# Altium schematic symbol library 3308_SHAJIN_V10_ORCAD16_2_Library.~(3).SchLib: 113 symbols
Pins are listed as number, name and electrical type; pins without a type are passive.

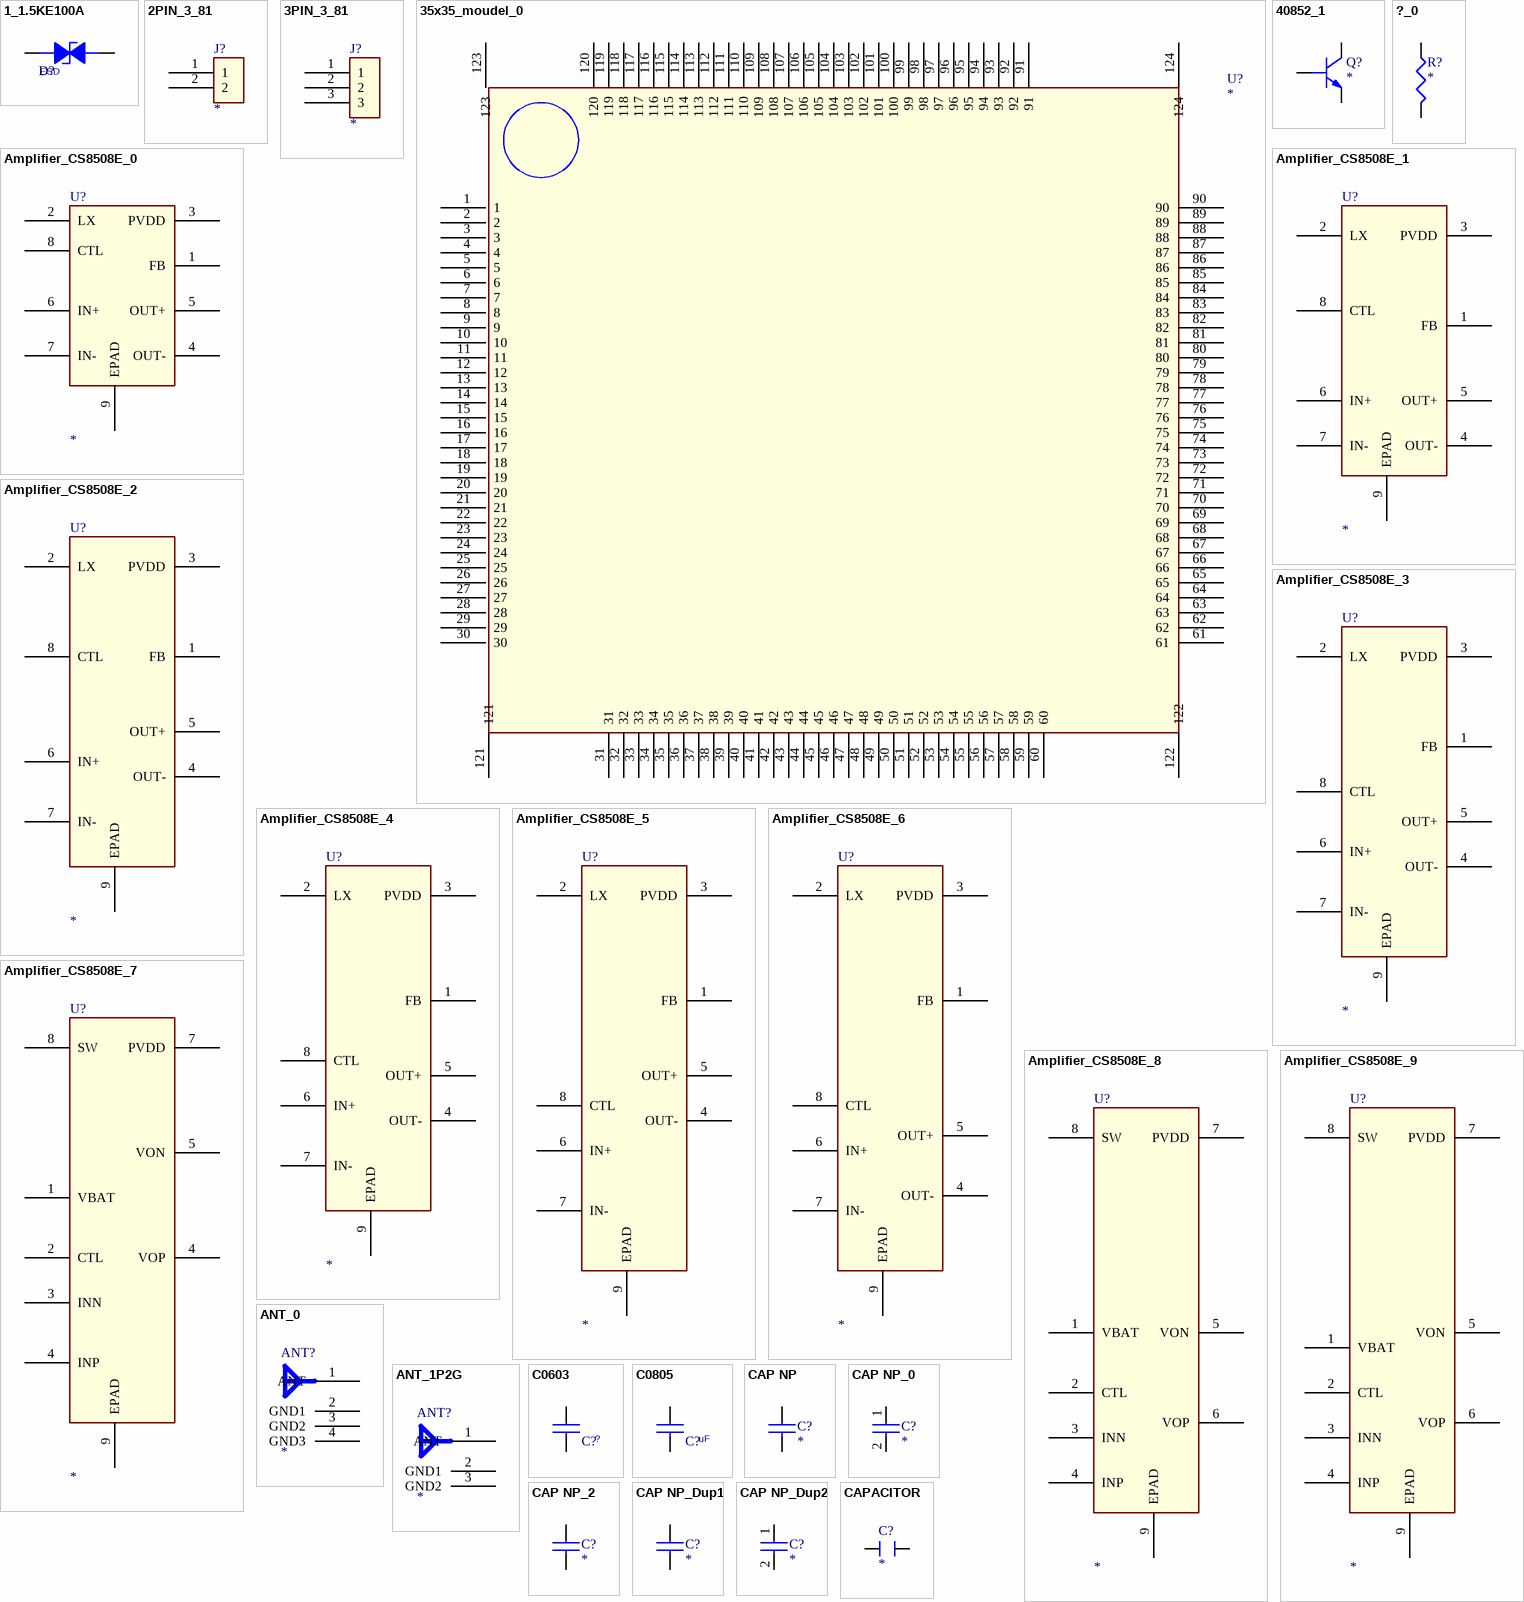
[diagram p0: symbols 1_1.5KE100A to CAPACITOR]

## 1_1.5KE100A
designator D?, comment ESD
Altium-Right: 40; Altium-Bottom: 20
pins: 1 ANODE, 2 CATHODE

## 2PIN_3_81
designator J?
Altium-Right: 50
footprint 2PIN_3_81
pins: 1, 2

## 3PIN_3_81
designator J?
Altium-Right: 50
footprint 3PIN_3_81
pins: 1, 2, 3

## 35x35_moudel_0
designator U?
Altium-Right: 462; Altium-Bottom: 430
footprint 35x35_moudel
pins: 1, 2, 3, 4, 5, 6, 7, 8, 9, 10, 11, 12, 13, 14, 15, 16, 17, 18, 19, 20, 21, 22, 23, 24, 25, 26, 27, 28, 29, 30, 31, 32, 33, 34, 35, 36, 37, 38, 39, 40, 41, 42, 43, 44, 45, 46, 47, 48, 49, 50, 51, 52, 53, 54, 55, 56, 57, 58, 59, 60, 61, 62, 63, 64, 65, 66, 67, 68, 69, 70, 71, 72, 73, 74, 75, 76, 77, 78, 79, 80, 81, 82, 83, 84, 85, 86, 87, 88, 89, 90, 91, 92, 93, 94, 95, 96, 97, 98, 99, 100, 101, 102, 103, 104, 105, 106, 107, 108, 109, 110, 111, 112, 113, 114, 115, 116, 117, 118, 119, 120, 121, 122, 123, 124

## 40852_1
designator Q?
Altium-Right: 20
pins: 1 B, 2 E, 3 C

## ?_0
designator R?
Altium-Right: 20; Altium-Bottom: 30
footprint R0402
pins: 1, 2

## Amplifier_CS8508E_0
designator U?
Altium-Right: 70; Altium-Bottom: 120
pins: 1 FB, 2 LX, 3 PVDD, 4 OUT-, 5 OUT+, 6 IN+, 7 IN-, 8 CTL, 9 EPAD

## Amplifier_CS8508E_1
designator U?
Altium-Right: 70; Altium-Bottom: 180
pins: 1 FB, 2 LX, 3 PVDD, 4 OUT-, 5 OUT+, 6 IN+, 7 IN-, 8 CTL, 9 EPAD

## Amplifier_CS8508E_2
designator U?
Altium-Right: 70; Altium-Bottom: 220
pins: 1 FB, 2 LX, 3 PVDD, 4 OUT-, 5 OUT+, 6 IN+, 7 IN-, 8 CTL, 9 EPAD

## Amplifier_CS8508E_3
designator U?
Altium-Right: 70; Altium-Bottom: 220
pins: 1 FB, 2 LX, 3 PVDD, 4 OUT-, 5 OUT+, 6 IN+, 7 IN-, 8 CTL, 9 EPAD

## Amplifier_CS8508E_4
designator U?
Altium-Right: 70; Altium-Bottom: 230
pins: 1 FB, 2 LX, 3 PVDD, 4 OUT-, 5 OUT+, 6 IN+, 7 IN-, 8 CTL, 9 EPAD

## Amplifier_CS8508E_5
designator U?
Altium-Right: 70; Altium-Bottom: 270
pins: 1 FB, 2 LX, 3 PVDD, 4 OUT-, 5 OUT+, 6 IN+, 7 IN-, 8 CTL, 9 EPAD

## Amplifier_CS8508E_6
designator U?
Altium-Right: 70; Altium-Bottom: 270
pins: 1 FB, 2 LX, 3 PVDD, 4 OUT-, 5 OUT+, 6 IN+, 7 IN-, 8 CTL, 9 EPAD

## Amplifier_CS8508E_7
designator U?
Altium-Right: 70; Altium-Bottom: 270
pins: 1 VBAT, 2 CTL, 3 INN, 4 INP, 4 VOP, 5 VON, 7 PVDD, 8 SW, 9 EPAD

## Amplifier_CS8508E_8
designator U?
Altium-Right: 70; Altium-Bottom: 270
pins: 1 VBAT, 2 CTL, 3 INN, 4 INP, 5 VON, 6 VOP, 7 PVDD, 8 SW, 9 EPAD

## Amplifier_CS8508E_9
designator U?
Altium-Right: 70; Altium-Bottom: 270
pins: 1 VBAT, 2 CTL, 3 INN, 4 INP, 5 VON, 6 VOP, 7 PVDD, 8 SW, 9 EPAD

## ANT_0
designator ANT?
Altium-Right: 30; Altium-Bottom: 60
pins: 1 ANT, 2 GND1, 3 GND2, 4 GND3

## ANT_1P2G
designator ANT?
Altium-Right: 30; Altium-Bottom: 50
pins: 1 ANT, 2 GND1, 3 GND2

## C0603
designator C?, comment ?
Altium-Right: 20; Altium-Bottom: 10
footprint C0603
pins: 1, 2

## C0805
designator C?, comment uF
Altium-Right: 20; Altium-Bottom: 10
footprint C0805
pins: 1, 2

## CAP NP
designator C?
Altium-Right: 20; Altium-Bottom: 10
pins: 1, 2

## CAP NP_0
designator C?
Altium-Right: 20; Altium-Bottom: 10
pins: 1, 2

## CAP NP_2
designator C?
Altium-Right: 20; Altium-Bottom: 10
pins: 1, 2

## CAP NP_Dup1
designator C?
Altium-Right: 20; Altium-Bottom: 10
footprint C0402
pins: 1, 2

## CAP NP_Dup2
designator C?
Altium-Right: 20; Altium-Bottom: 10
pins: 1, 2

## CAPACITOR
designator C?
Altium-Right: 10; Altium-Bottom: 20
pins: 1, 2

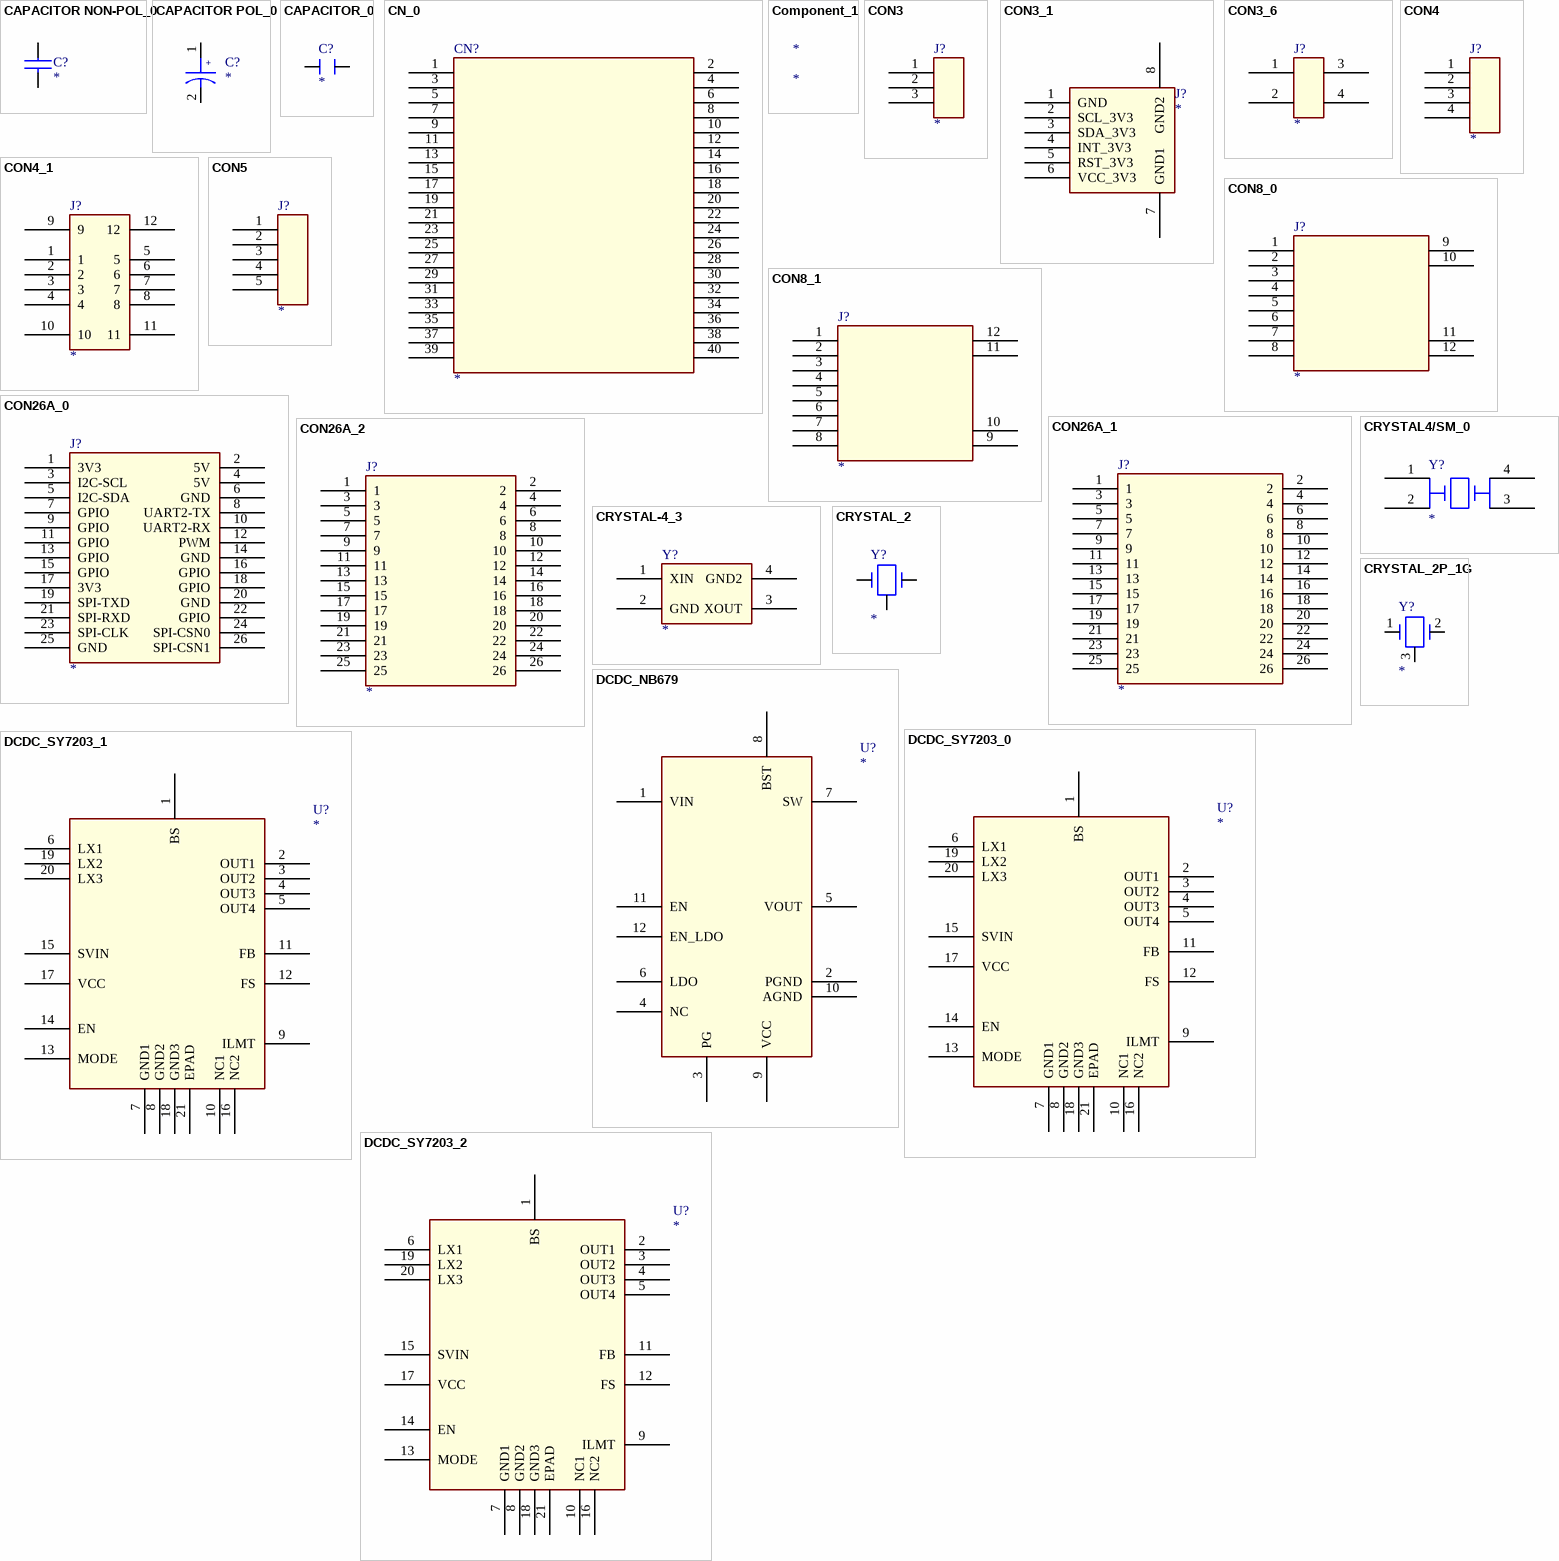
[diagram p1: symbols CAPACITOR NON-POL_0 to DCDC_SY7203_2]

## CAPACITOR NON-POL_0
designator C?
Altium-Right: 20; Altium-Bottom: 10
pins: 1, 2

## CAPACITOR POL_0
designator C?
Altium-Right: 20
pins: 1, 2

## CAPACITOR_0
designator C?
Altium-Right: 10; Altium-Bottom: 20
pins: 1, 2

## CN_0
designator CN?
Altium-Right: 160; Altium-Bottom: 210
pins: 1 GND, 2 GND, 3 UART0-CTS, 4 PWR-BTN-N, 5 UART0-TX, 6 RST-BTN-N, 7 UART0-RX, 8 SPI0-SCLK, 9 UART0-RTS, 10 SPI0-DIN, 11 UART1-TX, 12 SPI0-CS, 13 UART1-RX, 14 SPI0-DOUT, 15 I2C0-SCL, 16 PCM-FS/I2S-WC, 17 I2C0-SDA, 18 PCM-CLK/I2S-BC, 19 I2C1-SCL, 20 PCM-DO/I2S-DO, 21 I2C1-SDA, 22 PCM-DI/I2S-DI, 23 GPIO-A, 24 GPIO-B, 25 GPIO-C, 26 GPIO-D, 27 GPIO-E, 28 GPIO-F, 29 GPIO-G, 30 GPIO-H, 31 GPIO-I, 32 GPIO-J, 33 GPIO-K, 34 GPIO-L, 35 +1V8, 36 SYS-DCIN, 37 +5V, 38 SYS-DCIN, 39 GND, 40 GND

## Component_1
designator *

## CON3
designator J?
Altium-Right: 20; Altium-Bottom: 40
pins: 1, 2, 3

## CON3_1
designator J?
Altium-Right: 70
footprint DIP3_1X3_2R54
pins: 1 GND, 2 SCL_3V3, 3 SDA_3V3, 4 INT_3V3, 5 RST_3V3, 6 VCC_3V3, 7 GND1, 8 GND2

## CON3_6
designator J?
Altium-Right: 20; Altium-Bottom: 40
pins: 1, 2, 3, 4

## CON4
designator J?
Altium-Right: 20; Altium-Bottom: 50
pins: 1, 2, 3, 4

## CON4_1
designator J?
Altium-Right: 40; Altium-Bottom: 90
pins: 1, 2, 3, 4, 5, 6, 7, 8, 9, 10, 11, 12

## CON5
designator J?
Altium-Right: 20; Altium-Bottom: 60
pins: 1, 2, 3, 4, 5

## CON8_0
designator J?
Altium-Right: 90
pins: 1, 2, 3, 4, 5, 6, 7, 8, 9, 10, 11, 12

## CON8_1
designator J?
Altium-Right: 90
pins: 1, 2, 3, 4, 5, 6, 7, 8, 9, 10, 11, 12

## CON26A_0
designator J?
Altium-Right: 100; Altium-Bottom: 140
pins: 1 3V3, 2 5V, 3 I2C-SCL, 4 5V, 5 I2C-SDA, 6 GND, 7 GPIO, 8 UART2-TX, 9 GPIO, 10 UART2-RX, 11 GPIO, 12 PWM, 13 GPIO, 14 GND, 15 GPIO, 16 GPIO, 17 3V3, 18 GPIO, 19 SPI-TXD, 20 GND, 21 SPI-RXD, 22 GPIO, 23 SPI-CLK, 24 SPI-CSN0, 25 GND, 26 SPI-CSN1

## CON26A_1
designator J?
Altium-Right: 110; Altium-Bottom: 140
pins: 1, 2, 3, 4, 5, 6, 7, 8, 9, 10, 11, 12, 13, 14, 15, 16, 17, 18, 19, 20, 21, 22, 23, 24, 25, 26

## CON26A_2
designator J?
Altium-Right: 100; Altium-Bottom: 140
pins: 1, 2, 3, 4, 5, 6, 7, 8, 9, 10, 11, 12, 13, 14, 15, 16, 17, 18, 19, 20, 21, 22, 23, 24, 25, 26

## CRYSTAL4/SM_0
designator Y?
Altium-Right: 40
pins: 1, 2, 3, 4

## CRYSTAL-4_3
designator Y?
Altium-Right: 60; Altium-Bottom: 40
footprint CRY-3225
pins: 1 XIN, 2 GND, 3 XOUT, 4 GND2

## CRYSTAL_2
designator Y?
Altium-Right: 20
pins: 1, 2, 3, 4

## CRYSTAL_2P_1G
designator Y?
Altium-Right: 20
pins: 1, 2, 3

## DCDC_NB679
designator U?
Altium-Right: 100; Altium-Bottom: 200
footprint QFN12_3R00X2R00X0R90
pins: 1 VIN, 2 PGND, 3 PG, 4 NC, 5 VOUT, 6 LDO, 7 SW, 8 BST, 9 VCC, 10 AGND, 11 EN, 12 EN_LDO

## DCDC_SY7203_0
designator U?
Altium-Right: 130; Altium-Bottom: 180
footprint QFN8-2X2
pins: 1 BS, 2 OUT1, 3 OUT2, 4 OUT3, 5 OUT4, 6 LX1, 7 GND1, 8 GND2, 9 ILMT, 10 NC1, 11 FB, 12 FS, 13 MODE, 14 EN, 15 SVIN, 16 NC2, 17 VCC, 18 GND3, 19 LX2, 20 LX3, 21 EPAD

## DCDC_SY7203_1
designator U?
Altium-Right: 130; Altium-Bottom: 180
footprint QFN8-2X2
pins: 1 BS, 2 OUT1, 3 OUT2, 4 OUT3, 5 OUT4, 6 LX1, 7 GND1, 8 GND2, 9 ILMT, 10 NC1, 11 FB, 12 FS, 13 MODE, 14 EN, 15 SVIN, 16 NC2, 17 VCC, 18 GND3, 19 LX2, 20 LX3, 21 EPAD

## DCDC_SY7203_2
designator U?
Altium-Right: 130; Altium-Bottom: 180
footprint QFN8-2X2
pins: 1 BS, 2 OUT1, 3 OUT2, 4 OUT3, 5 OUT4, 6 LX1, 7 GND1, 8 GND2, 9 ILMT, 10 NC1, 11 FB, 12 FS, 13 MODE, 14 EN, 15 SVIN, 16 NC2, 17 VCC, 18 GND3, 19 LX2, 20 LX3, 21 EPAD

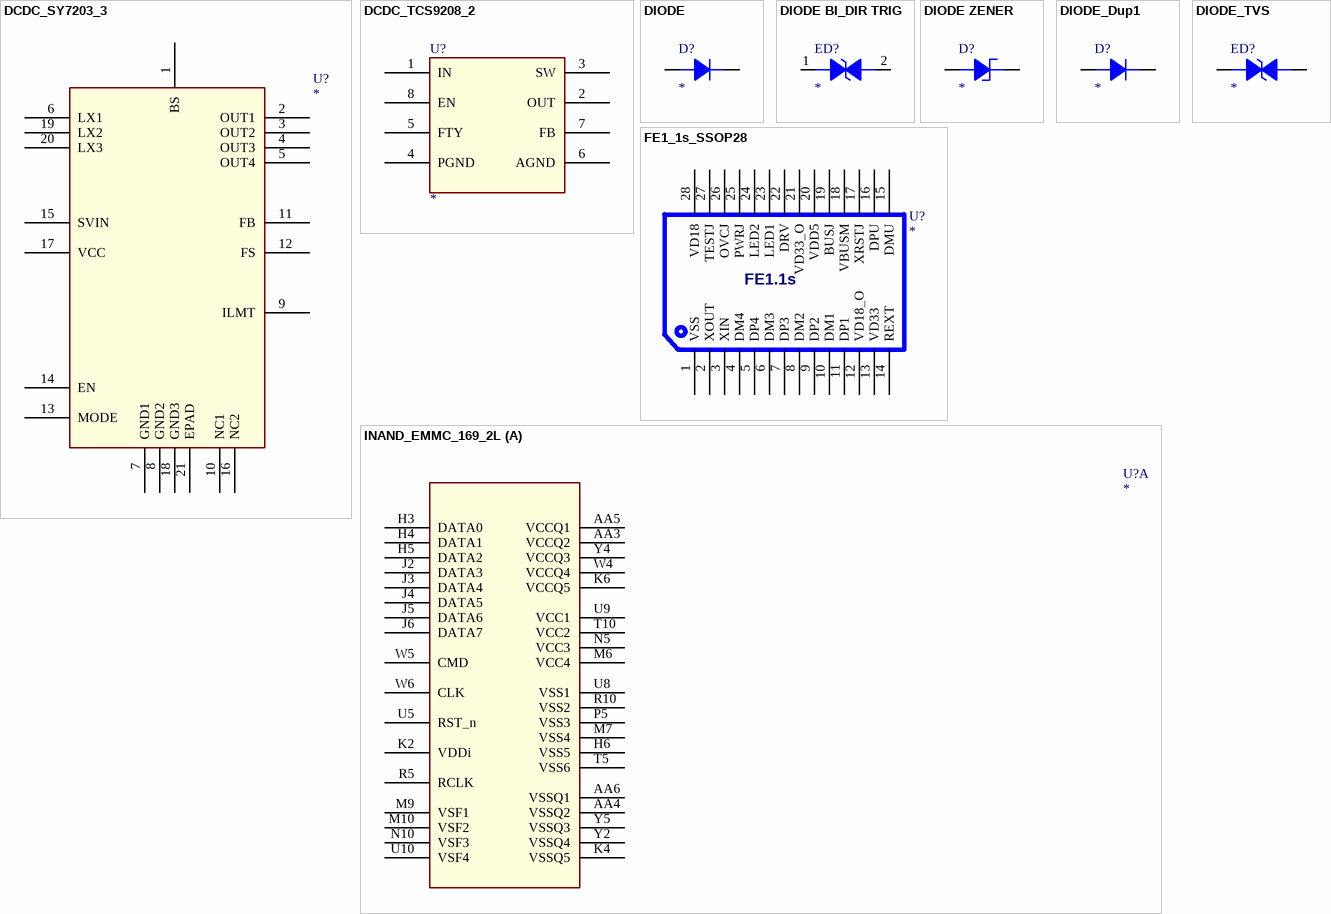
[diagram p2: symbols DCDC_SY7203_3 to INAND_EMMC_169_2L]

## DCDC_SY7203_3
designator U?
Altium-Right: 130; Altium-Bottom: 240
footprint QFN8-2X2
pins: 1 BS, 2 OUT1, 3 OUT2, 4 OUT3, 5 OUT4, 6 LX1, 7 GND1, 8 GND2, 9 ILMT, 10 NC1, 11 FB, 12 FS, 13 MODE, 14 EN, 15 SVIN, 16 NC2, 17 VCC, 18 GND3, 19 LX2, 20 LX3, 21 EPAD

## DCDC_TCS9208_2
designator U?
Altium-Right: 90
pins: 1 IN, 2 OUT, 3 SW, 4 PGND, 5 FTY, 6 AGND, 7 FB, 8 EN

## DIODE
designator D?
Altium-Right: 30; Altium-Bottom: 20
pins: 1 A, 2 K

## DIODE BI_DIR TRIG
designator ED?
Altium-Right: 40; Altium-Bottom: 20
pins: 1, 2

## DIODE ZENER
designator D?
Altium-Right: 30; Altium-Bottom: 20
pins: 1 ANODE, 2 CATHODE

## DIODE_Dup1
designator D?
Altium-Right: 30; Altium-Bottom: 20
pins: 1 A, 2 K

## DIODE_TVS
designator ED?
Altium-Right: 40; Altium-Bottom: 20
footprint E0402
pins: 1, 2

## FE1_1s_SSOP28
designator U?
Altium-Right: 160; Altium-Bottom: 90
pins: 1 VSS, 2 XOUT, 3 XIN, 4 DM4, 5 DP4, 6 DM3, 7 DP3, 8 DM2, 9 DP2, 10 DM1, 11 DP1, 12 VD18_O, 13 VD33, 14 REXT, 15 DMU, 16 DPU, 17 XRSTJ, 18 VBUSM, 19 BUSJ, 20 VDD5, 21 VD33_O, 22 DRV, 23 LED1, 24 LED2, 25 PWRJ, 26 OVCJ, 27 TESTJ, 28 VD18

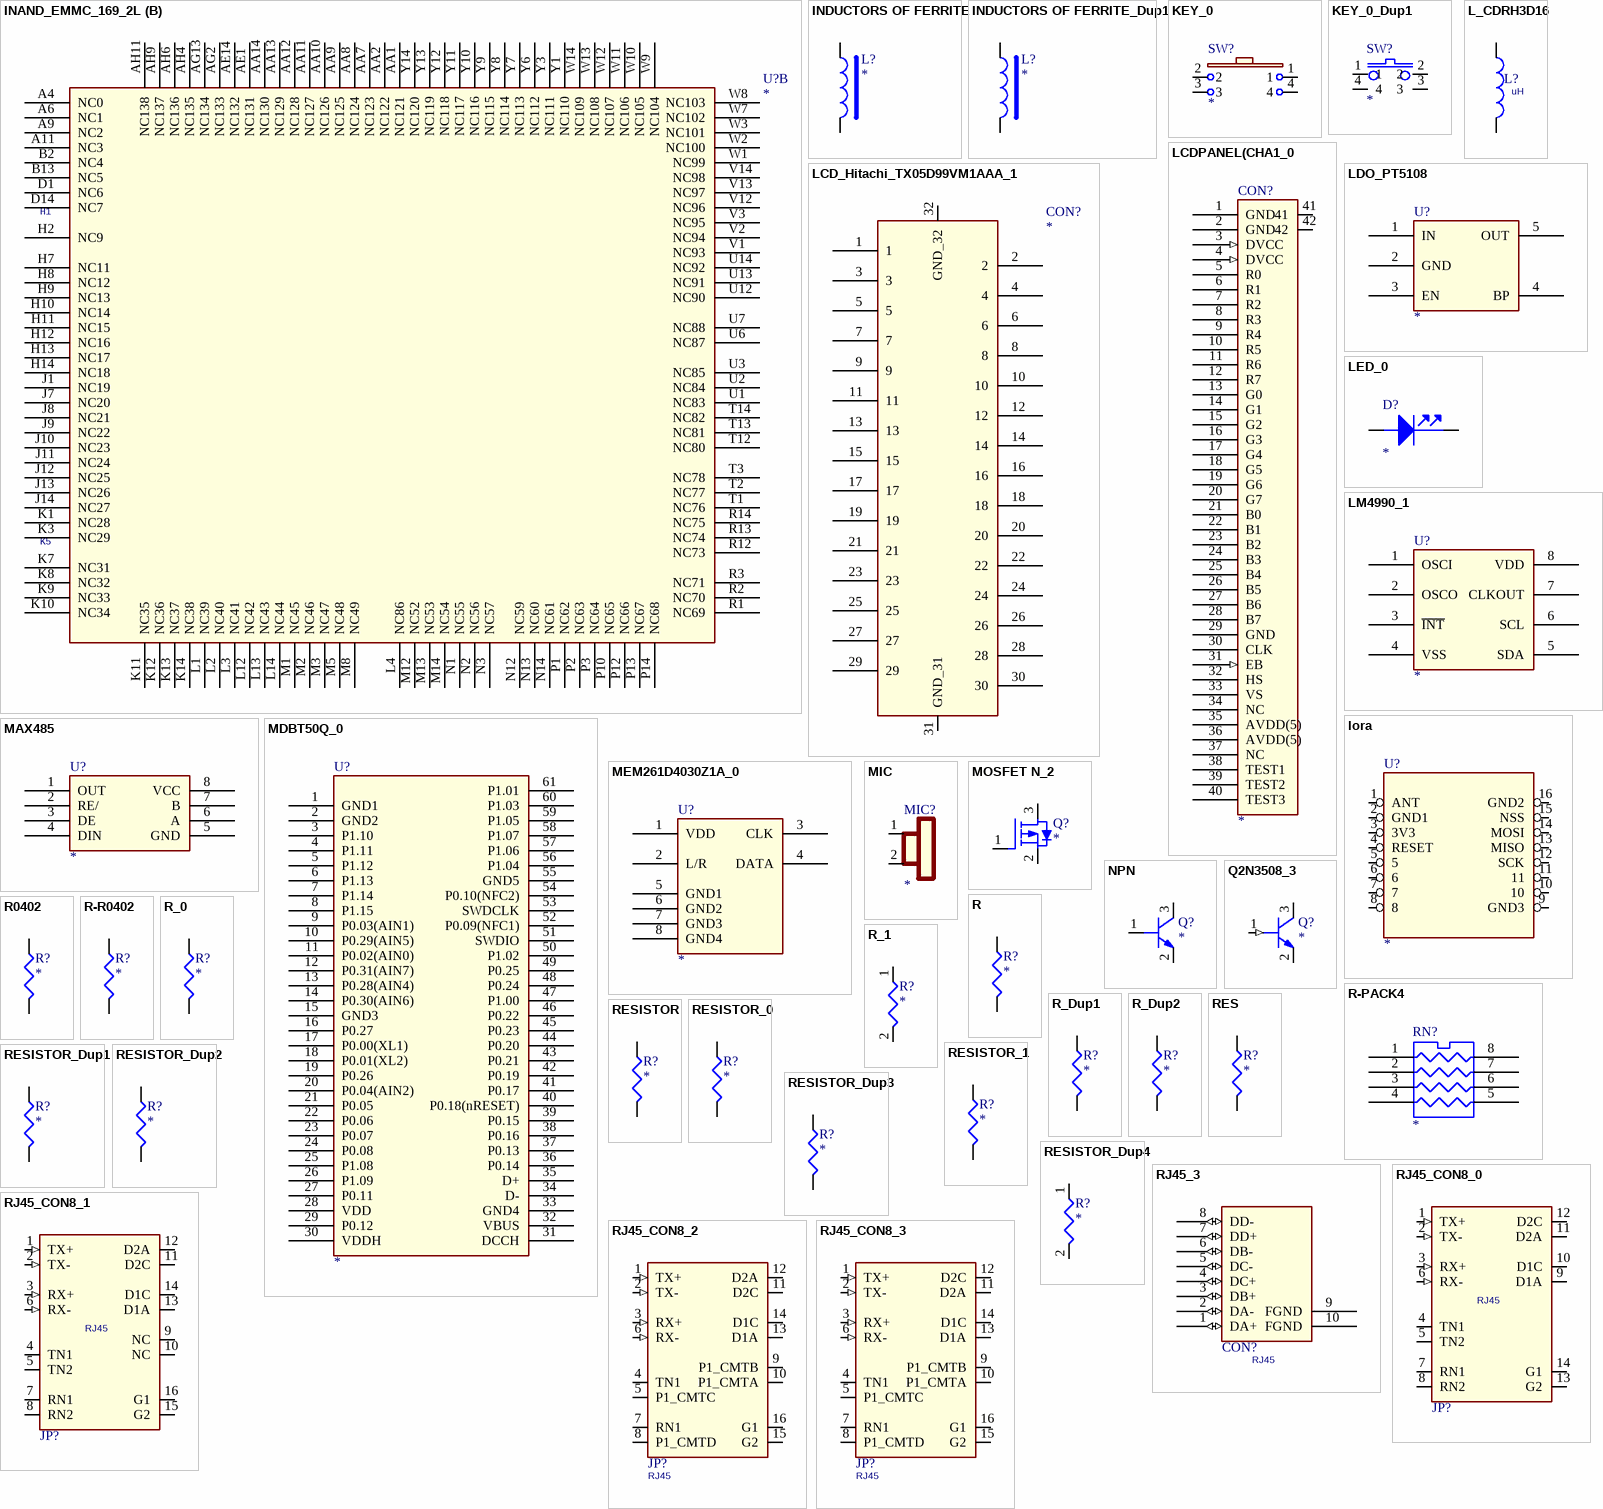
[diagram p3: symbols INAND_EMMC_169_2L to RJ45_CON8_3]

## INAND_EMMC_169_2L
designator U?
Altium-Right: 100; Altium-Bottom: 270; Altium-Right1: 430; Altium-Bottom1: 370
part A pins: AA3 VCCQ2, AA4 VSSQ2, AA5 VCCQ1, AA6 VSSQ1, H3 DATA0, H4 DATA1, H5 DATA2, H6 VSS5, J2 DATA3, J3 DATA4, J4 DATA5, J5 DATA6, J6 DATA7, K2 VDDi, K4 VSSQ5, K6 VCCQ5, M6 VCC4, M7 VSS4, M9 VSF1, M10 VSF2, N5 VCC3, N10 VSF3, P5 VSS3, R5 RCLK, R10 VSS2, T5 VSS6, T10 VCC2, U5 RST_n, U8 VSS1, U9 VCC1, U10 VSF4, W4 VCCQ4, W5 CMD, W6 CLK, Y2 VSSQ4, Y4 VCCQ3, Y5 VSSQ3
part B pins: A4 NC0, A6 NC1, A9 NC2, A11 NC3, AA1 NC121, AA2 NC122, AA7 NC123, AA8 NC124, AA9 NC125, AA10 NC126, AA11 NC127, AA12 NC128, AA13 NC129, AA14 NC130, AE1 NC131, AE14 NC132, AG2 NC133, AG13 NC134, AH4 NC135, AH6 NC136, AH9 NC137, AH11 NC138, B2 NC4, B13 NC5, D1 NC6, D14 NC7, H2 NC9, H7 NC11, H8 NC12, H9 NC13, H10 NC14, H11 NC15, H12 NC16, H13 NC17, H14 NC18, J1 NC19, J7 NC20, J8 NC21, J9 NC22, J10 NC23, J11 NC24, J12 NC25, J13 NC26, J14 NC27, K1 NC28, K3 NC29, K7 NC31, K8 NC32, K9 NC33, K10 NC34, K11 NC35, K12 NC36, K13 NC37, K14 NC38, L1 NC39, L2 NC40, L3 NC41, L4 NC86, L12 NC42, L13 NC43, L14 NC44, M1 NC45, M2 NC46, M3 NC47, M5 NC48, M8 NC49, M12 NC52, M13 NC53, M14 NC54, N1 NC55, N2 NC56, N3 NC57, N12 NC59, N13 NC60, N14 NC61, P1 NC62, P2 NC63, P3 NC64, P10 NC65, P12 NC66, P13 NC67, P14 NC68, R1 NC69, R2 NC70, R3 NC71, R12 NC73, R13 NC74, R14 NC75, T1 NC76, T2 NC77, T3 NC78, T12 NC80, T13 NC81, T14 NC82, U1 NC83, U2 NC84, U3 NC85, U6 NC87, U7 NC88, U12 NC90, U13 NC91, U14 NC92, V1 NC93, V2 NC94, V3 NC95, V12 NC96, V13 NC97, V14 NC98, W1 NC99, W2 NC100, W3 NC101, W7 NC102, W8 NC103, W9 NC104, W10 NC105, W11 NC106, W12 NC107, W13 NC108, W14 NC109, Y1 NC110, Y3 NC111, Y6 NC112, Y7 NC113, Y8 NC114, Y9 NC115, Y10 NC116, Y11 NC117, Y12 NC118, Y13 NC119, Y14 NC120

## INDUCTORS OF FERRITE
designator L?
Altium-Right: 20; Altium-Bottom: 40
pins: 1, 2

## INDUCTORS OF FERRITE_Dup1
designator L?
Altium-Right: 20; Altium-Bottom: 40
pins: 1, 2

## KEY_0
designator SW?
Altium-Right: 50; Altium-Bottom: 40
footprint YC-6615B
pins: 1, 2, 3, 4

## KEY_0_Dup1
designator SW?
Altium-Right: 30; Altium-Bottom: 20
pins: 1, 2, 3, 4

## L_CDRH3D16
designator L?, comment uH
Altium-Right: 10; Altium-Bottom: 40
footprint CDRH3D16
pins: 1, 2

## LCD_Hitachi_TX05D99VM1AAA_1
designator CON?
Altium-Right: 80; Altium-Bottom: 330
pins: 1, 2, 3, 4, 5, 6, 7, 8, 9, 10, 11, 12, 13, 14, 15, 16, 17, 18, 19, 20, 21, 22, 23, 24, 25, 26, 27, 28, 29, 30, 31 GND_31, 32 GND_32

## LCDPANEL(CHA1_0
designator CON?
Altium-Right: 40; Altium-Bottom: 410
footprint CON30
pins: 1 GND (power), 2 GND (power), 3 DVCC (in), 4 DVCC (in), 5 R0, 6 R1, 7 R2, 8 R3, 9 R4, 10 R5, 11 R6, 12 R7, 13 G0, 14 G1, 15 G2, 16 G3, 17 G4, 18 G5, 19 G6, 20 G7, 21 B0, 22 B1, 23 B2, 24 B3, 25 B4, 26 B5, 27 B6, 28 B7, 29 GND (power), 30 CLK (power), 31 EB (in), 32 HS (power), 33 VS (power), 34 NC, 35 AVDD(5), 36 AVDD(5), 37 NC, 38 TEST1, 39 TEST2, 40 TEST3, 41, 42

## LDO_PT5108
designator U?
Altium-Right: 70; Altium-Bottom: 60
pins: 1 IN, 2 GND, 3 EN, 4 BP, 5 OUT

## LED_0
designator D?
Altium-Right: 40; Altium-Bottom: 20
pins: 1 ANODE, 2 CATHODE

## LM4990_1
designator U?
Altium-Right: 80
pins: 1 OSCI, 2 OSCO, 3 ~{INT}, 4 VSS, 5 SDA, 6 SCL, 7 CLKOUT, 8 VDD

## lora
designator U?
Altium-Right: 100; Altium-Bottom: 110
footprint lora
pins: 1 ANT, 2 GND1, 3 3V3, 4 RESET, 5, 6, 7, 8, 9 GND3, 10, 11, 12 SCK, 13 MISO, 14 MOSI, 15 NSS, 16 GND2

## MAX485
designator U?
Altium-Right: 80; Altium-Bottom: 50
footprint MAX485
pins: 1 OUT, 2 RE/, 3 DE, 4 DIN, 5 GND, 6 A, 7 B, 8 VCC

## MDBT50Q_0
designator U?
Altium-Right: 130; Altium-Bottom: 320
pins: 1 GND1, 2 GND2, 3 P1.10, 4 P1.11, 5 P1.12, 6 P1.13, 7 P1.14, 8 P1.15, 9 P0.03(AIN1), 10 P0.29(AIN5), 11 P0.02(AIN0), 12 P0.31(AIN7), 13 P0.28(AIN4), 14 P0.30(AIN6), 15 GND3, 16 P0.27, 17 P0.00(XL1), 18 P0.01(XL2), 19 P0.26, 20 P0.04(AIN2), 21 P0.05, 22 P0.06, 23 P0.07, 24 P0.08, 25 P1.08, 26 P1.09, 27 P0.11, 28 VDD, 29 P0.12, 30 VDDH, 31 DCCH, 32 VBUS, 33 GND4, 34 D-, 35 D+, 36 P0.14, 37 P0.13, 38 P0.16, 39 P0.15, 40 P0.18(nRESET), 41 P0.17, 42 P0.19, 43 P0.21, 44 P0.20, 45 P0.23, 46 P0.22, 47 P1.00, 48 P0.24, 49 P0.25, 50 P1.02, 51 SWDIO, 52 P0.09(NFC1), 53 SWDCLK, 54 P0.10(NFC2), 55 GND5, 56 P1.04, 57 P1.06, 58 P1.07, 59 P1.05, 60 P1.03, 61 P1.01

## MEM261D4030Z1A_0
designator U?
Altium-Right: 70; Altium-Bottom: 90
pins: 1 VDD, 2 L/R, 3 CLK, 4 DATA, 5 GND1, 6 GND2, 7 GND3, 8 GND4

## MIC
designator MIC?
Altium-Right: 20; Altium-Bottom: 40
pins: 1, 2

## MOSFET N_2
designator Q?
Altium-Right: 30; Altium-Bottom: 20
pins: 1 GATE, 2 SOURCE, 3 DRAIN

## NPN
designator Q?
Altium-Right: 20
pins: 1 BASE, 2 EMITTER, 3 COLLECTOR

## Q2N3508_3
designator Q?
Altium-Right: 20
pins: 1 BASE (in), 2 EMITTER, 3 COLLECTOR

## R
designator R?
Altium-Right: 20; Altium-Bottom: 30
pins: 1, 2

## R0402
designator R?
Altium-Right: 20; Altium-Bottom: 30
footprint R0402
pins: 1, 2

## R-PACK4
designator RN?
Altium-Right: 40; Altium-Bottom: 50
pins: 1 R1, 2 R2, 3 R3, 4 R4, 5 R4, 6 R3, 7 R2, 8 R1

## R-R0402
designator R?
Altium-Right: 20; Altium-Bottom: 30
footprint R0402
pins: 1, 2

## R_0
designator R?
Altium-Right: 20; Altium-Bottom: 30
pins: 1, 2

## R_1
designator R?
Altium-Right: 20; Altium-Bottom: 30
pins: 1, 2

## R_Dup1
designator R?
OriginalSymbolOrigin: (0,0); Altium-Right: 20; Altium-Bottom: 30
pins: 1, 2

## R_Dup2
designator R?
Altium-Right: 20; Altium-Bottom: 30
pins: 1, 2

## RES
designator R?
Altium-Right: 20; Altium-Bottom: 30
pins: 1, 2

## RESISTOR
designator R?
Altium-Right: 20; Altium-Bottom: 30
pins: 1, 2

## RESISTOR_0
designator R?
Altium-Right: 20; Altium-Bottom: 30
pins: 1, 2

## RESISTOR_1
designator R?
Altium-Right: 20; Altium-Bottom: 30
pins: 1, 2

## RESISTOR_Dup1
designator R?
Altium-Right: 20; Altium-Bottom: 30
footprint R0402
pins: 1, 2

## RESISTOR_Dup2
designator R?
Altium-Right: 20; Altium-Bottom: 30
pins: 1, 2

## RESISTOR_Dup3
designator R?
Altium-Right: 20; Altium-Bottom: 30
pins: 1, 2

## RESISTOR_Dup4
designator R?
Altium-Right: 20; Altium-Bottom: 30
footprint R0402
pins: 1, 2

## RJ45_3
designator CON?, comment RJ45
Altium-Right: 60; Altium-Bottom: 90
pins: 1 DA+ (io), 2 DA- (io), 3 DB+ (io), 4 DC+ (io), 5 DC- (io), 6 DB- (io), 7 DD+ (io), 8 DD- (io), 9 FGND (power), 10 FGND (power)

## RJ45_CON8_0
designator JP?, comment RJ45
Altium-Right: 80; Altium-Bottom: 130
footprint RJ45_CON8
pins: 1 TX+ (in), 2 TX- (in), 3 RX+ (in), 4 TN1 (hiz), 5 TN2 (hiz), 6 RX- (in), 7 RN1 (hiz), 8 RN2 (hiz), 9 D1A, 10 D1C, 11 D2A, 12 D2C, 13 G2, 14 G1

## RJ45_CON8_1
designator JP?, comment RJ45
Altium-Right: 80; Altium-Bottom: 130
footprint RJ45_CON8
pins: 1 TX+ (in), 2 TX- (in), 3 RX+ (in), 4 TN1 (hiz), 5 TN2 (hiz), 6 RX- (in), 7 RN1 (hiz), 8 RN2 (hiz), 9 NC, 10 NC, 11 D2C, 12 D2A, 13 D1A, 14 D1C, 15 G2, 16 G1

## RJ45_CON8_2
designator JP?, comment RJ45
Altium-Right: 80; Altium-Bottom: 130
footprint RJ45_CON8
pins: 1 TX+ (in), 2 TX- (in), 3 RX+ (in), 4 TN1 (hiz), 5 P1_CMTC (hiz), 6 RX- (in), 7 RN1 (hiz), 8 P1_CMTD (hiz), 9 P1_CMTB, 10 P1_CMTA, 11 D2C, 12 D2A, 13 D1A, 14 D1C, 15 G2, 16 G1

## RJ45_CON8_3
designator JP?, comment RJ45
Altium-Right: 80; Altium-Bottom: 130
footprint RJ45_CON8
pins: 1 TX+ (in), 2 TX- (in), 3 RX+ (in), 4 TN1 (hiz), 5 P1_CMTC (hiz), 6 RX- (in), 7 RN1 (hiz), 8 P1_CMTD (hiz), 9 P1_CMTB, 10 P1_CMTA, 11 D2A, 12 D2C, 13 D1A, 14 D1C, 15 G2, 16 G1

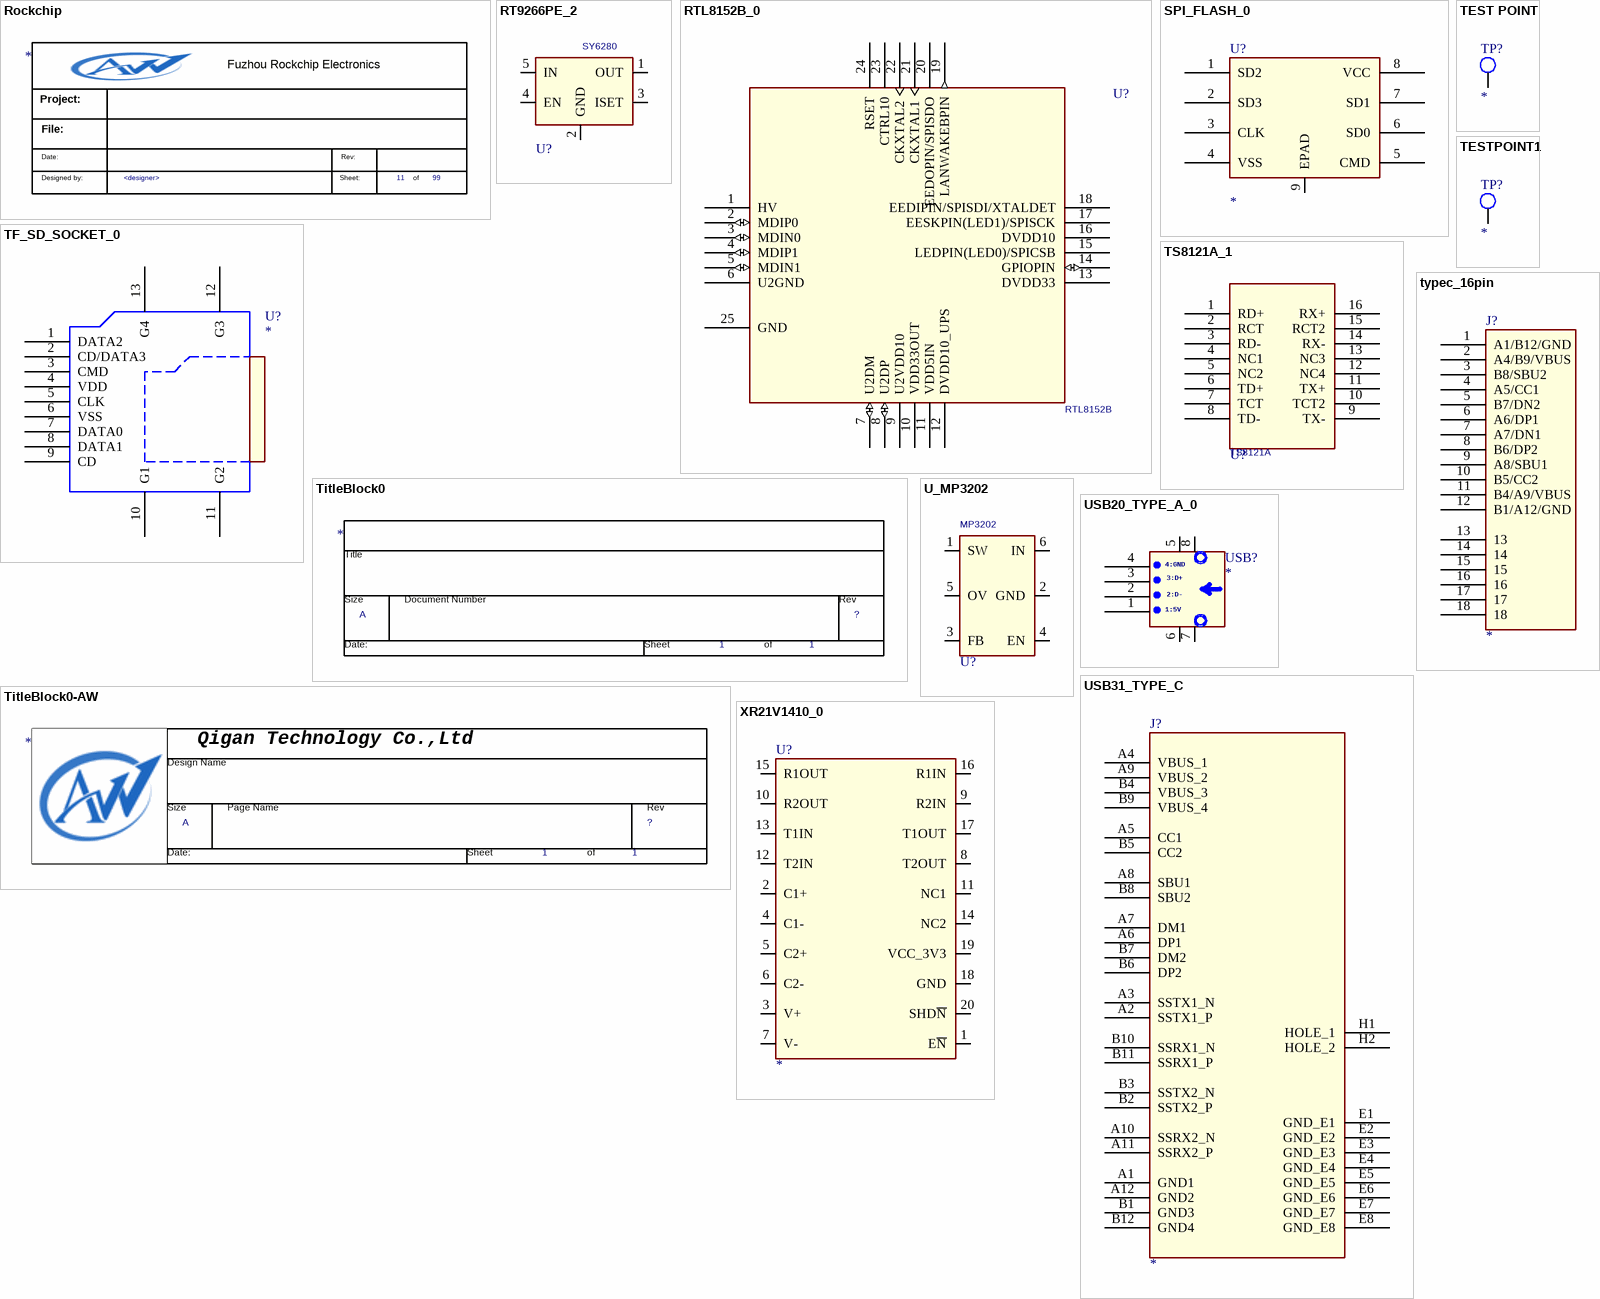
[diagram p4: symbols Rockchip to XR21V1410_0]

## Rockchip
designator *  Designer: <designer>  Schematic Page Number: 11  Schematic Page Count: 99  (graphical)
Altium-Right: 290; Altium-Bottom: 101

## RT9266PE_2
designator U?, comment SY6280
Altium-Right: 65; Altium-Bottom: 45
footprint SOT23-6
pins: 1 OUT, 2 GND, 3 ISET, 4 EN, 5 IN

## RTL8152B_0
designator U?, comment RTL8152B
Altium-Right: 210
pins: 1 HV (power), 2 MDIP0 (io), 3 MDIN0 (io), 4 MDIP1 (io), 5 MDIN1 (io), 6 U2GND (power), 7 U2DM (io), 8 U2DP (io), 9 U2VDD10 (power), 10 VDD33OUT (power), 11 VDD5IN (power), 12 DVDD10_UPS (power), 13 DVDD33 (power), 14 GPIOPIN (io), 15 LEDPIN(LED0)/SPICSB, 16 DVDD10 (power), 17 EESKPIN(LED1)/SPISCK, 18 EEDIPIN/SPISDI/XTALDET, 19 LANWAKEBPIN (out), 20 EEDOPIN/SPISDO, 21 CKXTAL1, 22 CKXTAL2, 23 CTRL10 (power), 24 RSET, 25 GND (power)

## SPI_FLASH_0
designator U?
Altium-Right: 100; Altium-Bottom: 80
pins: 1 SD2, 2 SD3, 3 CLK, 4 VSS, 5 CMD, 6 SD0, 7 SD1, 8 VCC, 9 EPAD

## TEST POINT
designator TP?
Altium-Right: 10
pins: 1

## TESTPOINT1
designator TP?
Altium-Right: 20; Altium-Bottom: 10
footprint TEST
pins: 1

## TF_SD_SOCKET_0
designator U?
Altium-Right: 130; Altium-Bottom: 120
footprint TF-CKT01-009D
pins: 1 DATA2, 2 CD/DATA3, 3 CMD, 4 VDD, 5 CLK, 6 VSS, 7 DATA0, 8 DATA1, 9 CD, 10 G1, 11 G2, 12 G3, 13 G4

## TitleBlock0
designator *  Page Size: A  Page Number: 1  (graphical)
Altium-Right: 360; Altium-Bottom: 90

## TitleBlock0-AW
designator *  Page Size: A  Page Number: 1  (graphical)
Altium-Right: 450; Altium-Bottom: 90

## TS8121A_1
designator U?, comment TS8121A
Altium-Right: 70; Altium-Bottom: 110
pins: 1 RD+, 2 RCT, 3 RD-, 4 NC1, 5 NC2, 6 TD+, 7 TCT, 8 TD-, 9 TX-, 10 TCT2, 11 TX+, 12 NC4, 13 NC3, 14 RX-, 15 RCT2, 16 RX+

## typec_16pin
designator J?
Altium-Right: 60; Altium-Bottom: 200
footprint typec_16pin
pins: 1 A1/B12/GND, 2 A4/B9/VBUS, 3 B8/SBU2, 4 A5/CC1, 5 B7/DN2, 6 A6/DP1, 7 A7/DN1, 8 B6/DP2, 9 A8/SBU1, 10 B5/CC2, 11 B4/A9/VBUS, 12 B1/A12/GND, 13, 14, 15, 16, 17, 18

## U_MP3202
designator U?, comment MP3202
Altium-Right: 50; Altium-Bottom: 80
footprint SOT-23-6
pins: 1 SW, 2 GND, 3 FB, 4 EN, 5 OV, 6 IN

## USB20_TYPE_A_0
designator USB?
Altium-Right: 50
footprint USB20
pins: 1, 2, 3, 4, 5, 6, 7, 8

## USB31_TYPE_C
designator J?
Altium-Right: 130; Altium-Bottom: 350
pins: A1 GND1, A2 SSTX1_P, A3 SSTX1_N, A4 VBUS_1, A5 CC1, A6 DP1, A7 DM1, A8 SBU1, A9 VBUS_2, A10 SSRX2_N, A11 SSRX2_P, A12 GND2, B1 GND3, B2 SSTX2_P, B3 SSTX2_N, B4 VBUS_3, B5 CC2, B6 DP2, B7 DM2, B8 SBU2, B9 VBUS_4, B10 SSRX1_N, B11 SSRX1_P, B12 GND4, E1 GND_E1, E2 GND_E2, E3 GND_E3, E4 GND_E4, E5 GND_E5, E6 GND_E6, E7 GND_E7, E8 GND_E8, H1 HOLE_1, H2 HOLE_2

## XR21V1410_0
designator U?
Altium-Right: 120; Altium-Bottom: 200
pins: 1 E~{N}, 2 C1+, 3 V+, 4 C1-, 5 C2+, 6 C2-, 7 V-, 8 T2OUT, 9 R2IN, 10 R2OUT, 11 NC1, 12 T2IN, 13 T1IN, 14 NC2, 15 R1OUT, 16 R1IN, 17 T1OUT, 18 GND, 19 VCC_3V3, 20 SHD~{N}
